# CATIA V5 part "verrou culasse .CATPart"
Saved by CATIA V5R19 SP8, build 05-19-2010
Part number: verrou culasse 
Bounding box of the stored display mesh (mm): x -14 to 14, y 0 to 1.75, z 0 to 5
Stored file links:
  C:\Users\Arthur\Desktop\Catia parts\GLOCK\Poignée\verrou culasse .CATPart
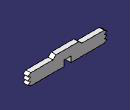
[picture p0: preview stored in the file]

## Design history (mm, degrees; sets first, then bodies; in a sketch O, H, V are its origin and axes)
Body1 (main body)
  Sketch1 on zx-plane, origin (0, 0, 0), H (-1, 0, 0), V (0, 0, 1)
    point P1 (13, 0)
    point P2 (-13, 0)
    point P3 (-13, 4)
    point P4 (13, 4)
    line L1 (13, 4) -> (5.118, 4)
    point P5 (5.118, 4)
    line L2 (5.118, 4) -> (4, 5)
    point P6 (4, 5)
    line L3 (4, 5) -> (-4, 5)
    point P7 (-4, 5)
    line L4 (-13, 4) -> (-5.118, 4)
    point P8 (-5.118, 4)
    line L5 (-4, 5) -> (-5.118, 4)
    line L6 (13, 0) -> (1.25, 0)
    line L7 (1.25, 0) -> (1.25, 2)
    line L8 (1.25, 2) -> (-1.25, 2)
    line L9 (-1.25, 2) -> (-1.25, 0)
    point P12 (-1.25, 0)
    line L10 (-1.25, 0) -> (-13, 0)
    line L11 (-13, 4) -> (-14, 3.2855)
    point P13 (-14, 3.2855)
    line L12 (-14, 3.2855) -> (-13, 2.67)
    point P14 (-14, 3.2855)
    point P15 (-13, 2.67)
    line L13 (-13, 2.67) -> (-14, 1.9555)
    point P16 (-13, 2.67)
    point P17 (-14, 1.9555)
    line L14 (-14, 1.9555) -> (-13, 1.33)
    point P18 (-14, 1.9555)
    point P19 (-13, 1.33)
    line L15 (-13, 1.33) -> (-14, 0.6555)
    point P20 (-14, 0.6555)
    line L16 (-14, 0.6555) -> (-13, 0)
    point P21 (-14, 0.6555)
    point P22 (-13, 0)
    construction line L17 (-14, 4.1296) -> (-14, 0.1203)
    point P23 (-14, 4.1296)
    point P24 (-14, 0.1203)
    axis line L18 (-13, 4.8376) -> (-13, -0.3366)
    point P26 (-13, -0.3366)
    point P27 (13, 0)
    point P28 (13, 4)
    point P29 (14, 3.2855)
    point P30 (14, 3.2855)
    point P31 (13, 2.67)
    point P32 (13, 2.67)
    point P33 (14, 1.9555)
    point P34 (14, 1.9555)
    point P35 (13, 1.33)
    point P36 (14, 0.6555)
    point P37 (14, 0.6555)
    point P38 (13, 0)
    point P39 (14, 0.1203)
    point P40 (14, 4.1296)
    construction line L19 (14, 4.1296) -> (14, 0.1203)
    point P41 (13, -0.3366)
    line L20 (13, 4) -> (14, 3.2855)
    line L21 (14, 3.2855) -> (13, 2.67)
    line L22 (13, 2.67) -> (14, 1.9555)
    line L23 (14, 1.9555) -> (13, 1.33)
    line L24 (13, 1.33) -> (14, 0.6555)
    line L25 (14, 0.6555) -> (13, 0)
    distance L6 L8 = 2
    length L3 = 8
    distance L7 L9 = 2.5
    distance L3 L1 = 1
    distance P5 P6 = 1.5
    distance P15 L4 = 1.33
    distance P19 L10 = 1.33
    distance P20 P17 = 1.3
    distance P13 P17 = 1.33
    distance L18 L17 = 1
    distance L19 L17 = 28
    distance L4 L10 = 4
    horizontal: L1 H, L3 H, L4 H, L6 H, L8 H, L10 H
    symmetry: P8 P5 V, P6 P7 V, L9 L7 V, P2 P27 V, P3 P28 V, P13 P29 V, P14 P30 V, P15 P31 V, P16 P32 V, P17 P33 V, P18 P34 V, P19 P35 V, P20 P36 V, P21 P37 V, P22 P38 V, P24 P39 V, P23 P40 V, L17 L19 V, P26 P41 V, L11 L20 V, L12 L21 V, L13 L22 V, L14 L23 V, L15 L24 V, L16 L25 V
    vertical: L7 V, L9 V, L17 V, L18 V
    coincidence: P12 L6, L10 H, P21 L15, P22 P2, P18 P17, P13 P14, P20 P21, L18 P2, P3 L18, P19 L18, L18 P15, P16 P15, P20 L17, P17 L17, P13 L17, P4 P28, P1 P27, P1 P38, P29 P30, P31 P32, P33 P34, P36 P37
  Pad1: profile Sketch1, direction (0, 1, 0), length 1.75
